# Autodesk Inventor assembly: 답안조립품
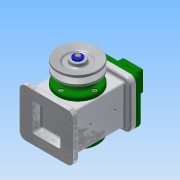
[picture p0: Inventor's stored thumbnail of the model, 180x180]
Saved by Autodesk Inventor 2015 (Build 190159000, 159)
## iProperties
Created: 2017-08
Part Number: 답안조립품
Document SubType Name: Assembly
Designer: Administrator
Author: Administrator
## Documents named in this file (18)
- C:\Users\Administrator\Desktop\답안조립품.iam
- C:\Users\Administrator\Desktop\본체.ipt
- C:\Users\Administrator\Desktop\470807V1013\베어링 17 x 40 x 12.ipt
- C:\Users\Administrator\Desktop\470807V1013\앞커버.ipt
- C:\Users\Administrator\Desktop\470807V1013\뒤커버.ipt
- C:\Users\Administrator\Desktop\470807V1013\편심축.ipt
- C:\Users\Administrator\Desktop\470807V1013\링크.ipt
- C:\Users\Administrator\Desktop\470807V1013\슬라이더.ipt
- C:\Users\Administrator\Desktop\470807V1013\클레비스 핀 6 x 22.ipt
- 클레비스 핀 6 x 22.ipt
- C:\Users\Administrator\Desktop\470807V1013\덮개.ipt
- C:\Users\Administrator\Desktop\470807V1013\볼트 M4 x 8.ipt
- C:\Users\Administrator\Desktop\470807V1013\E-링.ipt
- C:\Users\Administrator\Desktop\470807V1013\오일 실 17 30 8.ipt
- C:\Users\Administrator\Desktop\470807V1013\키 4 x 4 x 12.ipt
- C:\Users\Administrator\Desktop\470807V1013\V-벨트풀리.ipt
- C:\Users\Administrator\Desktop\470807V1013\와셔 4x16.ipt
- C:\Users\Administrator\Desktop\470807V1013\볼트 M4 x 10.ipt
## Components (2 placed, 2 different names)
1. E-링:1
2. V-벨트풀리:1 — 각도:2
## Component patterns: 구성요소 패턴 3:2 (2 elements)
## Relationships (1: Angle 1)
- 각도:2 [Angle]: V-벨트풀리:1
